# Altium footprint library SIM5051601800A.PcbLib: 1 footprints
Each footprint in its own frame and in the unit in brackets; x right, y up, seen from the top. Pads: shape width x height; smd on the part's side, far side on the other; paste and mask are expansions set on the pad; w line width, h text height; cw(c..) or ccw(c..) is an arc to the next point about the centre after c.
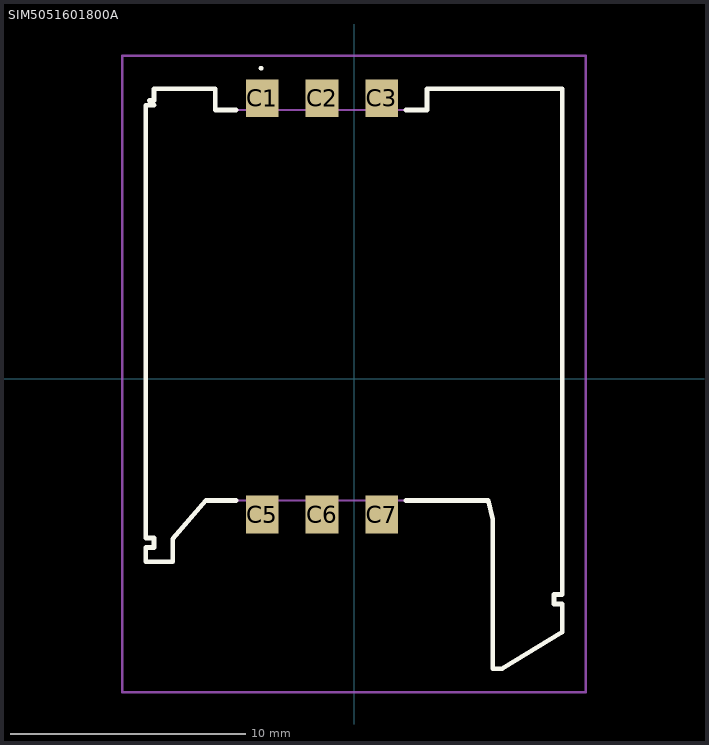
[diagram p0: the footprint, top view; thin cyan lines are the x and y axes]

## SIM5051601800A [mm]
pads (6):
  rect 1.4x1.6 smd: C1(-3.9,11.925) C2(-1.36,11.925) C3(1.18,11.925) C5(-3.9,-5.775) C6(-1.36,-5.775) C7(1.18,-5.775)
Top Overlay:
  lines w0.1: -4,13.2 -4,13.2 ; -4,13.2 ccw(c-3.95,13.2) -3.9,13.2 ; -4,13.2 cw(c-3.95,13.2) -3.9,13.2 ; -3.9,13.2 -3.9,13.2
  lines w0.2: -5,-5.175 -6.3,-5.175 -7.7,-6.8 -7.7,-7.775 -8.85,-7.775 -8.85,-7.175 -8.5,-7.175 -8.5,-6.775 -8.85,-6.775 -8.85,11.625 -8.5,11.625 -8.7,11.825 -8.5,11.825 -8.5,12.325 -5.9,12.325 -5.9,11.425 -5,11.425 ; 2.2,-5.175 5.7,-5.175 5.9,-5.975 5.9,-12.325 6.3,-12.325 8.85,-10.775 8.85,-9.575 8.5,-9.575 8.5,-9.175 8.85,-9.175 8.85,12.325 3.1,12.325 3.1,11.425 2.2,11.425
Mechanical 15:
  lines w0.1: -8.85,-7.775 -8.85,-7.175 -8.5,-7.175 -8.5,-6.775 -8.85,-6.775 -8.85,11.625 -8.5,11.625 -8.7,11.825 -8.5,11.825 -8.5,12.325 -5.9,12.325 -5.9,11.425 3.1,11.425 3.1,12.325 8.85,12.325 8.85,-9.175 8.5,-9.175 8.5,-9.575 8.85,-9.575 8.85,-10.775 6.3,-12.325 5.9,-12.325 5.9,-5.975 5.7,-5.175 -6.3,-5.175 -7.7,-6.775 -7.7,-7.775 -8.85,-7.775
Mechanical 20:
  lines w0.1: -9.85,-13.325 9.85,-13.325 9.85,13.725 -9.85,13.725 -9.85,-13.325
